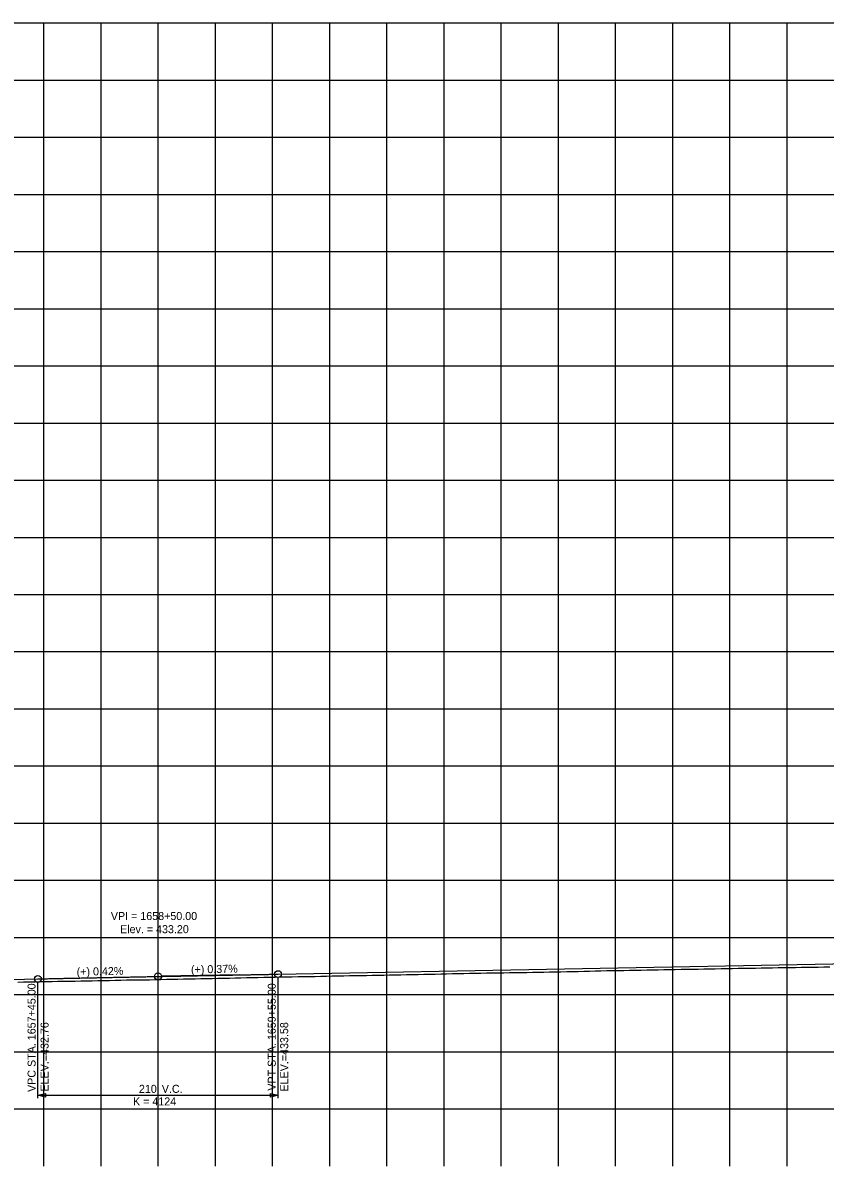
# Model space of a CAD drawing. Extents: x -90830 to 2015517, y -20856 to 836331.
# Drawn here: x 54655 to 55357, y -9797 to -8797 of the extents above; entities that cross this region are included whole.
import ezdxf

# ---------------------------------------------------------------- set-up
doc = ezdxf.new("R2010")
doc.units = 0
for name, color, linetype in [('Level 1', 7, 'Continuous'), ('RD_DDB_GradeTX', 7, 'Continuous'), ('RD_DDB_Profile_EX', 7, 'Continuous'), ('RD_DDB_Profile_Lbl', 7, 'Continuous'), ('RD_DDB_Profile_PR', 7, 'Continuous'), ('RD_DDB_StripGrade', 7, 'Continuous'), ('RD_DDB_VCLbl', 7, 'Continuous'), ('RD_PD_Final_TX', 7, 'Continuous')]:
    doc.layers.add(name, color=color, linetype=linetype)

msp = doc.modelspace()

# ---------------------------------------------------------------- linework, layer by layer
at = {"layer": 'Level 1'}
for p, q in [((54373.46, -8797.12), (55973.46, -8797.12)), ((54673.46, -8797.12), (54673.46, -9297.12)), ((54723.46, -8797.12), (54723.46, -9297.12)), ((54773.46, -8797.12), (54773.46, -9297.12)), ((54823.46, -8797.12), (54823.46, -9297.12)), ((54873.46, -8797.12), (54873.46, -9297.12)), ((54923.46, -8797.12), (54923.46, -9297.12)), ((54973.46, -8797.12), (54973.46, -9297.12)), ((55023.46, -8797.12), (55023.46, -9297.12)), ((55073.46, -8797.12), (55073.46, -9297.12)), ((55123.46, -8797.12), (55123.46, -9297.12)), ((55173.46, -8797.12), (55173.46, -9297.12)), ((55223.46, -8797.12), (55223.46, -9297.12)), ((55273.46, -8797.12), (55273.46, -9297.12)), ((55323.46, -8797.12), (55323.46, -9297.12)), ((54373.46, -8847.12), (55973.46, -8847.12)), ((54373.46, -8897.12), (55973.46, -8897.12)), ((54373.46, -8947.12), (55973.46, -8947.12)), ((54373.46, -8997.12), (55973.46, -8997.12)), ((54373.46, -9047.12), (55973.46, -9047.12)), ((54373.46, -9097.12), (55973.46, -9097.12)), ((54373.46, -9147.12), (55973.46, -9147.12)), ((54373.46, -9197.12), (55973.46, -9197.12)), ((54373.46, -9247.12), (55973.46, -9247.12)), ((54373.46, -9297.12), (55973.46, -9297.12)), ((54373.46, -9297.12), (55973.46, -9297.12)), ((54673.46, -9297.12), (54673.46, -9797.12)), ((54723.46, -9297.12), (54723.46, -9797.12)), ((54773.46, -9297.12), (54773.46, -9797.12)), ((54823.46, -9297.12), (54823.46, -9797.12)), ((54873.46, -9297.12), (54873.46, -9797.12)), ((54923.46, -9297.12), (54923.46, -9797.12)), ((54973.46, -9297.12), (54973.46, -9797.12)), ((55023.46, -9297.12), (55023.46, -9797.12)), ((55073.46, -9297.12), (55073.46, -9797.12)), ((55123.46, -9297.12), (55123.46, -9797.12)), ((55173.46, -9297.12), (55173.46, -9797.12)), ((55223.46, -9297.12), (55223.46, -9797.12)), ((55273.46, -9297.12), (55273.46, -9797.12)), ((55323.46, -9297.12), (55323.46, -9797.12)), ((54373.46, -9347.12), (55973.46, -9347.12)), ((54373.46, -9397.12), (55973.46, -9397.12)), ((54373.46, -9447.12), (55973.46, -9447.12)), ((54373.46, -9497.12), (55973.46, -9497.12)), ((54373.46, -9547.12), (55973.46, -9547.12)), ((54373.46, -9597.12), (55973.46, -9597.12)), ((54373.46, -9647.12), (55973.46, -9647.12)), ((54373.46, -9697.12), (55973.46, -9697.12)), ((54373.46, -9747.12), (55973.46, -9747.12))]:
    msp.add_line(p, q, dxfattribs=at)
at = {"layer": 'RD_DDB_GradeTX'}
for p, q in [((54844.45, -9629.83), (54776.46, -9631.08)), ((54702.48, -9632.62), (54770.46, -9631.2))]:
    msp.add_line(p, q, dxfattribs=at)
msp.add_circle((54773.46, -9631.13), 3, dxfattribs=at)
at = {"layer": 'RD_DDB_Profile_EX'}
for points in [[(54920.95, -9630.89), (54925.95, -9630.78), (54930.95, -9630.68), (54935.95, -9630.59), (54940.95, -9630.51), (54945.95, -9630.42), (54950.95, -9630.33), (54955.95, -9630.24), (54960.95, -9630.16), (54965.95, -9630.06), (54970.95, -9629.97), (54975.95, -9629.88), (54980.95, -9629.79), (54985.95, -9629.7), (54990.95, -9629.6), (54995.95, -9629.5), (55000.95, -9629.4), (55005.95, -9629.3), (55010.95, -9629.2), (55015.95, -9629.07), (55020.95, -9628.94), (55025.95, -9628.81), (55030.95, -9628.69), (55035.95, -9628.59), (55040.95, -9628.49), (55045.95, -9628.39), (55050.95, -9628.3), (55055.95, -9628.24), (55060.95, -9628.18), (55065.95, -9628.13), (55070.95, -9628.06), (55075.95, -9627.97), (55080.95, -9627.89), (55085.95, -9627.8), (55090.95, -9627.71), (55095.95, -9627.64), (55100.95, -9627.56), (55105.95, -9627.48), (55110.95, -9627.39), (55115.95, -9627.28), (55120.95, -9627.17), (55125.95, -9627.07), (55130.95, -9626.96), (55135.95, -9626.85), (55140.95, -9626.74), (55145.95, -9626.64), (55150.95, -9626.52), (55155.95, -9626.39), (55160.95, -9626.26), (55165.95, -9626.13), (55170.95, -9626.02), (55175.95, -9625.95), (55180.95, -9625.87), (55185.95, -9625.79), (55190.95, -9625.71), (55195.95, -9625.61), (55200.95, -9625.51), (55205.95, -9625.42), (55210.95, -9625.32), (55215.95, -9625.22), (55220.95, -9625.11), (55225.95, -9625.01), (55230.95, -9624.93), (55235.95, -9624.86), (55240.95, -9624.79), (55245.95, -9624.73), (55250.95, -9624.64), (55255.95, -9624.52), (55260.95, -9624.4), (55265.95, -9624.28), (55270.95, -9624.18), (55275.95, -9624.12), (55280.95, -9624.06), (55285.95, -9624), (55290.95, -9623.92), (55295.95, -9623.83), (55300.95, -9623.74), (55305.95, -9623.65), (55310.95, -9623.57), (55315.95, -9623.49), (55320.95, -9623.41), (55325.95, -9623.32), (55330.95, -9623.25), (55335.95, -9623.19), (55340.95, -9623.12), (55345.95, -9623.06), (55350.95, -9622.99), (55355.95, -9622.91), (55360.95, -9622.84)], [(54650.95, -9636.13), (54655.95, -9636.04), (54660.95, -9635.94), (54665.95, -9635.84), (54670.95, -9635.74), (54675.95, -9635.64), (54680.95, -9635.54), (54685.95, -9635.44), (54690.95, -9635.35), (54695.95, -9635.28), (54700.95, -9635.21), (54705.95, -9635.14), (54710.95, -9635.05), (54715.95, -9634.95), (54720.95, -9634.85), (54725.95, -9634.74), (54730.95, -9634.64), (54735.95, -9634.53), (54740.95, -9634.41), (54745.95, -9634.29), (54750.95, -9634.2), (54755.95, -9634.15), (54760.95, -9634.09), (54765.95, -9634.04), (54770.95, -9633.95), (54775.95, -9633.83), (54780.95, -9633.71), (54785.95, -9633.59), (54790.95, -9633.48), (54795.95, -9633.4), (54800.95, -9633.31), (54805.95, -9633.23), (54810.95, -9633.13), (54815.95, -9633.03), (54820.95, -9632.93), (54825.95, -9632.83), (54830.95, -9632.72), (54835.95, -9632.6), (54840.95, -9632.49), (54845.95, -9632.37), (54850.95, -9632.26), (54855.95, -9632.16), (54860.95, -9632.06), (54865.95, -9631.97), (54870.95, -9631.87), (54875.95, -9631.76), (54880.95, -9631.66), (54885.95, -9631.56), (54890.95, -9631.47), (54895.95, -9631.38), (54900.95, -9631.29), (54905.95, -9631.21), (54910.95, -9631.11), (54915.95, -9631), (54920.95, -9630.89)]]:
    msp.add_lwpolyline(points, dxfattribs=at)
at = {"layer": 'RD_DDB_Profile_PR'}
for p, q in [((54878.46, -9629.2), (55468.46, -9618.35)), ((54486.46, -9637.14), (54668.46, -9633.33))]:
    msp.add_line(p, q, dxfattribs=at)
msp.add_spline([(54668.46, -9633.33), (54672.66, -9633.24), (54676.86, -9633.16), (54681.06, -9633.07), (54685.26, -9632.98), (54689.46, -9632.89), (54693.66, -9632.81), (54697.86, -9632.72), (54702.06, -9632.63), (54706.26, -9632.55), (54710.46, -9632.46), (54714.66, -9632.38), (54718.86, -9632.29), (54723.06, -9632.21), (54727.26, -9632.12), (54731.46, -9632.04), (54735.66, -9631.95), (54739.86, -9631.87), (54744.06, -9631.78), (54748.26, -9631.7), (54752.46, -9631.62), (54756.66, -9631.53), (54760.86, -9631.45), (54765.06, -9631.37), (54769.26, -9631.28), (54773.46, -9631.2), (54777.66, -9631.12), (54781.86, -9631.03), (54786.06, -9630.95), (54790.26, -9630.87), (54794.46, -9630.79), (54798.66, -9630.71), (54802.86, -9630.63), (54807.06, -9630.55), (54811.26, -9630.46), (54815.46, -9630.38), (54819.66, -9630.3), (54823.86, -9630.22), (54828.06, -9630.14), (54832.26, -9630.06), (54836.46, -9629.98), (54840.66, -9629.91), (54844.86, -9629.83), (54849.06, -9629.75), (54853.26, -9629.67), (54857.46, -9629.59), (54861.66, -9629.51), (54865.86, -9629.43), (54870.06, -9629.36), (54874.26, -9629.28), (54878.46, -9629.2)], degree=3, dxfattribs=at)
at = {"layer": 'RD_DDB_VCLbl'}
for p, q in [((54668.46, -9737.64), (54668.46, -9636.33)), ((54878.46, -9737.64), (54878.46, -9632.2)), ((54668.46, -9735.14), (54878.46, -9735.14))]:
    msp.add_line(p, q, dxfattribs=at)
for centre in [(54878.46, -9629.2), (54668.46, -9633.33)]:
    msp.add_circle(centre, 3, dxfattribs=at)
at = {"layer": 'RD_PD_Final_TX'}
for points in [[(54675.06, -9736.79), (54668.46, -9735.14), (54675.06, -9733.49)], [(54871.86, -9733.49), (54878.46, -9735.14), (54871.86, -9736.79)]]:
    msp.add_lwpolyline(points, close=True, dxfattribs=at)

# ---------------------------------------------------------------- texts
at = {"layer": 'RD_DDB_GradeTX'}
for s, rotation, p in [('(+) 0.42%', 1.19944, (54702.43, -9630.62)), ('(+) 0.37%', 1.05363, (54802.41, -9628.6))]:
    msp.add_text(s, height=7, rotation=rotation, dxfattribs=at).set_placement(p)
at = {"layer": 'RD_DDB_Profile_Lbl'}
for s, p in [('VPI = 1658+50.00', (54732.27, -9581.85)), ('Elev. = 433.20', (54740.34, -9593.35))]:
    msp.add_text(s, height=7, dxfattribs=at).set_placement(p)
at = {"layer": 'RD_DDB_StripGrade'}
for s, p in [('VPC STA. 1657+45.00 ', (54666.44, -9732.23)), ('VPT STA. 1659+55.00 ', (54876.49, -9731.1)), ('ELEV.=432.76', (54677.81, -9731.85)), ('ELEV.=433.58', (54887.36, -9731.85))]:
    msp.add_text(s, height=7, rotation=90, dxfattribs=at).set_placement(p)
at = {"layer": 'RD_DDB_VCLbl'}
for s, p in [("210' V.C.", (54756.82, -9733.01)), ('K = 4124', (54751.66, -9744.02))]:
    msp.add_text(s, height=7, dxfattribs=at).set_placement(p)

doc.saveas('drawing.dxf')
